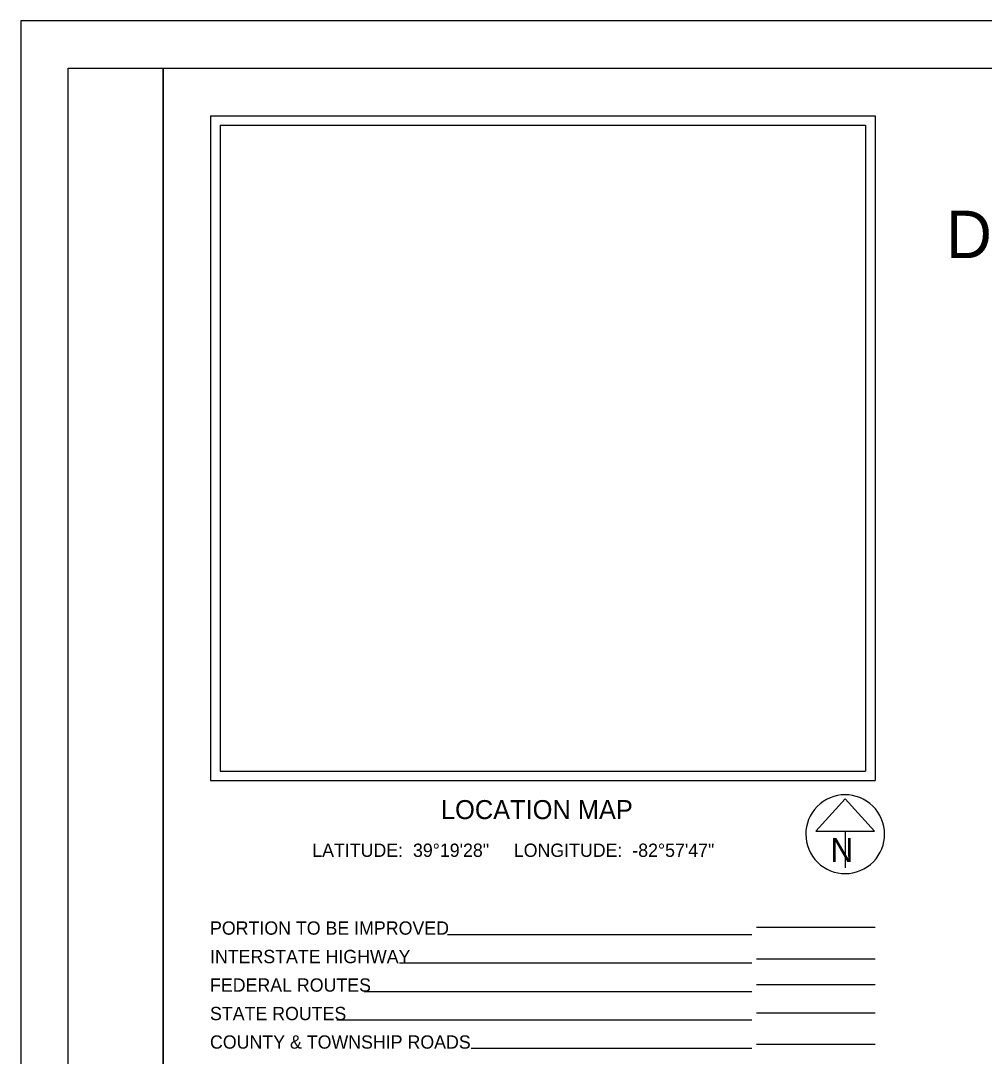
# Model space of a CAD drawing. Extents: x -6.6 to 34, y 0 to 22.
# Drawn here: x 0 to 10.15, y 11.1 to 22 of the extents above; entities that cross this region are included whole.
import ezdxf

# ---------------------------------------------------------------- set-up
doc = ezdxf.new("R2010")
doc.units = 0
for name, color, linetype in [('SH_Border', 7, 'Continuous'), ('SH_Cut_Line', 7, 'Continuous'), ('SH_Data', 7, 'Continuous'), ('SH_Text', 7, 'Continuous')]:
    doc.layers.add(name, color=color, linetype=linetype)

msp = doc.modelspace()

# ---------------------------------------------------------------- linework, layer by layer
at = {"layer": 'SH_Border'}
for points in [[(0.5, 21.5), (1.5, 21.5), (1.5, 0.5), (0.5, 0.5)], [(1.5, 21.5), (33.5, 21.5), (33.5, 0.5), (1.5, 0.5)]]:
    msp.add_lwpolyline(points, close=True, dxfattribs=at)
at = {"layer": 'SH_Cut_Line'}
msp.add_lwpolyline([(0, 0), (34, 0), (34, 22), (0, 22)], close=True, dxfattribs=at)
at = {"layer": 'SH_Data'}
for p, q in [((2, 21), (9, 21)), ((2, 21), (2, 14)), ((9, 21), (9, 14)), ((2.1, 20.9), (2.1, 14.1)), ((2.1, 20.9), (8.9, 20.9)), ((8.9, 20.9), (8.9, 14.1)), ((2.1, 14.1), (8.9, 14.1)), ((2.1, 14.1), (2.1, 14.1)), ((2, 14), (9, 14)), ((8.685, 13.809), (8.377, 13.468)), ((8.992, 13.468), (8.685, 13.809)), ((8.377, 13.468), (8.992, 13.468)), ((8.685, 13.468), (8.685, 13.081)), ((8.685, 13.435), (8.685, 13.435)), ((8.685, 13.435), (8.685, 13.435)), ((7.75, 12.455), (9, 12.455)), ((7.7, 12.377), (4.494, 12.377)), ((9, 12.121), (7.75, 12.121)), ((7.7, 12.077), (3.99, 12.077)), ((7.7, 11.777), (3.619, 11.777)), ((9, 11.849), (7.75, 11.849)), ((7.7, 11.477), (3.329, 11.477)), ((9, 11.549), (7.75, 11.549)), ((7.7, 11.177), (4.745, 11.177)), ((9, 11.222), (7.75, 11.222))]:
    msp.add_line(p, q, dxfattribs=at)
msp.add_arc((8.685, 13.435), 0.415, 129.7798, 129.7633, dxfattribs=at)

# ---------------------------------------------------------------- texts
msp.add_text('N', height=0.25, dxfattribs=at).set_placement((8.529, 13.144))
at = {"layer": 'SH_Text'}
for s, height, p in [('DEPARTMENT OF TRANSPORTATION', 0.5, (9.747, 19.5)), ('LOCATION MAP', 0.2, (4.427, 13.594)), ('LATITUDE:  39°19\'28"     LONGITUDE:  -82°57\'47"', 0.14, (3.071, 13.196)), ('PORTION TO BE IMPROVED', 0.14, (1.994, 12.377)), ('INTERSTATE HIGHWAY', 0.14, (1.994, 12.077)), ('FEDERAL ROUTES', 0.14, (1.994, 11.777)), ('STATE ROUTES', 0.14, (1.994, 11.477)), ('COUNTY & TOWNSHIP ROADS', 0.14, (1.994, 11.177))]:
    msp.add_text(s, height=height, dxfattribs=at).set_placement(p)

doc.saveas('drawing.dxf')
